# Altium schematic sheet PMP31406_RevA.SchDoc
size 431 x 279 mm; Date: Not shown in title block; ApprovedBy: Not shown in title block; CheckedBy: Not shown in title block; Author: Not shown in title block; CompanyName: Not shown in title block; Engineer: Not shown in title block; Organization: Not shown in title block; Address1: Not shown in title block; Address2: Not shown in title block; Address3: Not shown in title block; Address4: Not shown in title block; DocumentNumber: 2; Revision: Use project parameter SCH_Rev; SheetNumber: 1; SheetTotal: 1; PageSetup: Record=PageOptions¦CenterHorizontal=True¦CenterVertical=True¦PrintScale=1.00¦XCorrection=1.00¦YCorrection=1.00¦PrintKind=0¦BorderSize=5000000¦LeftOffset=0¦BottomOffset=0¦Orientation=2¦PaperLength=1000¦PaperWidth=1000¦Scale=100¦PaperSource=15¦PrintQuality=600¦MediaType=1¦DitherType=10¦PaperKind=Letter¦PrintScaleMode=1
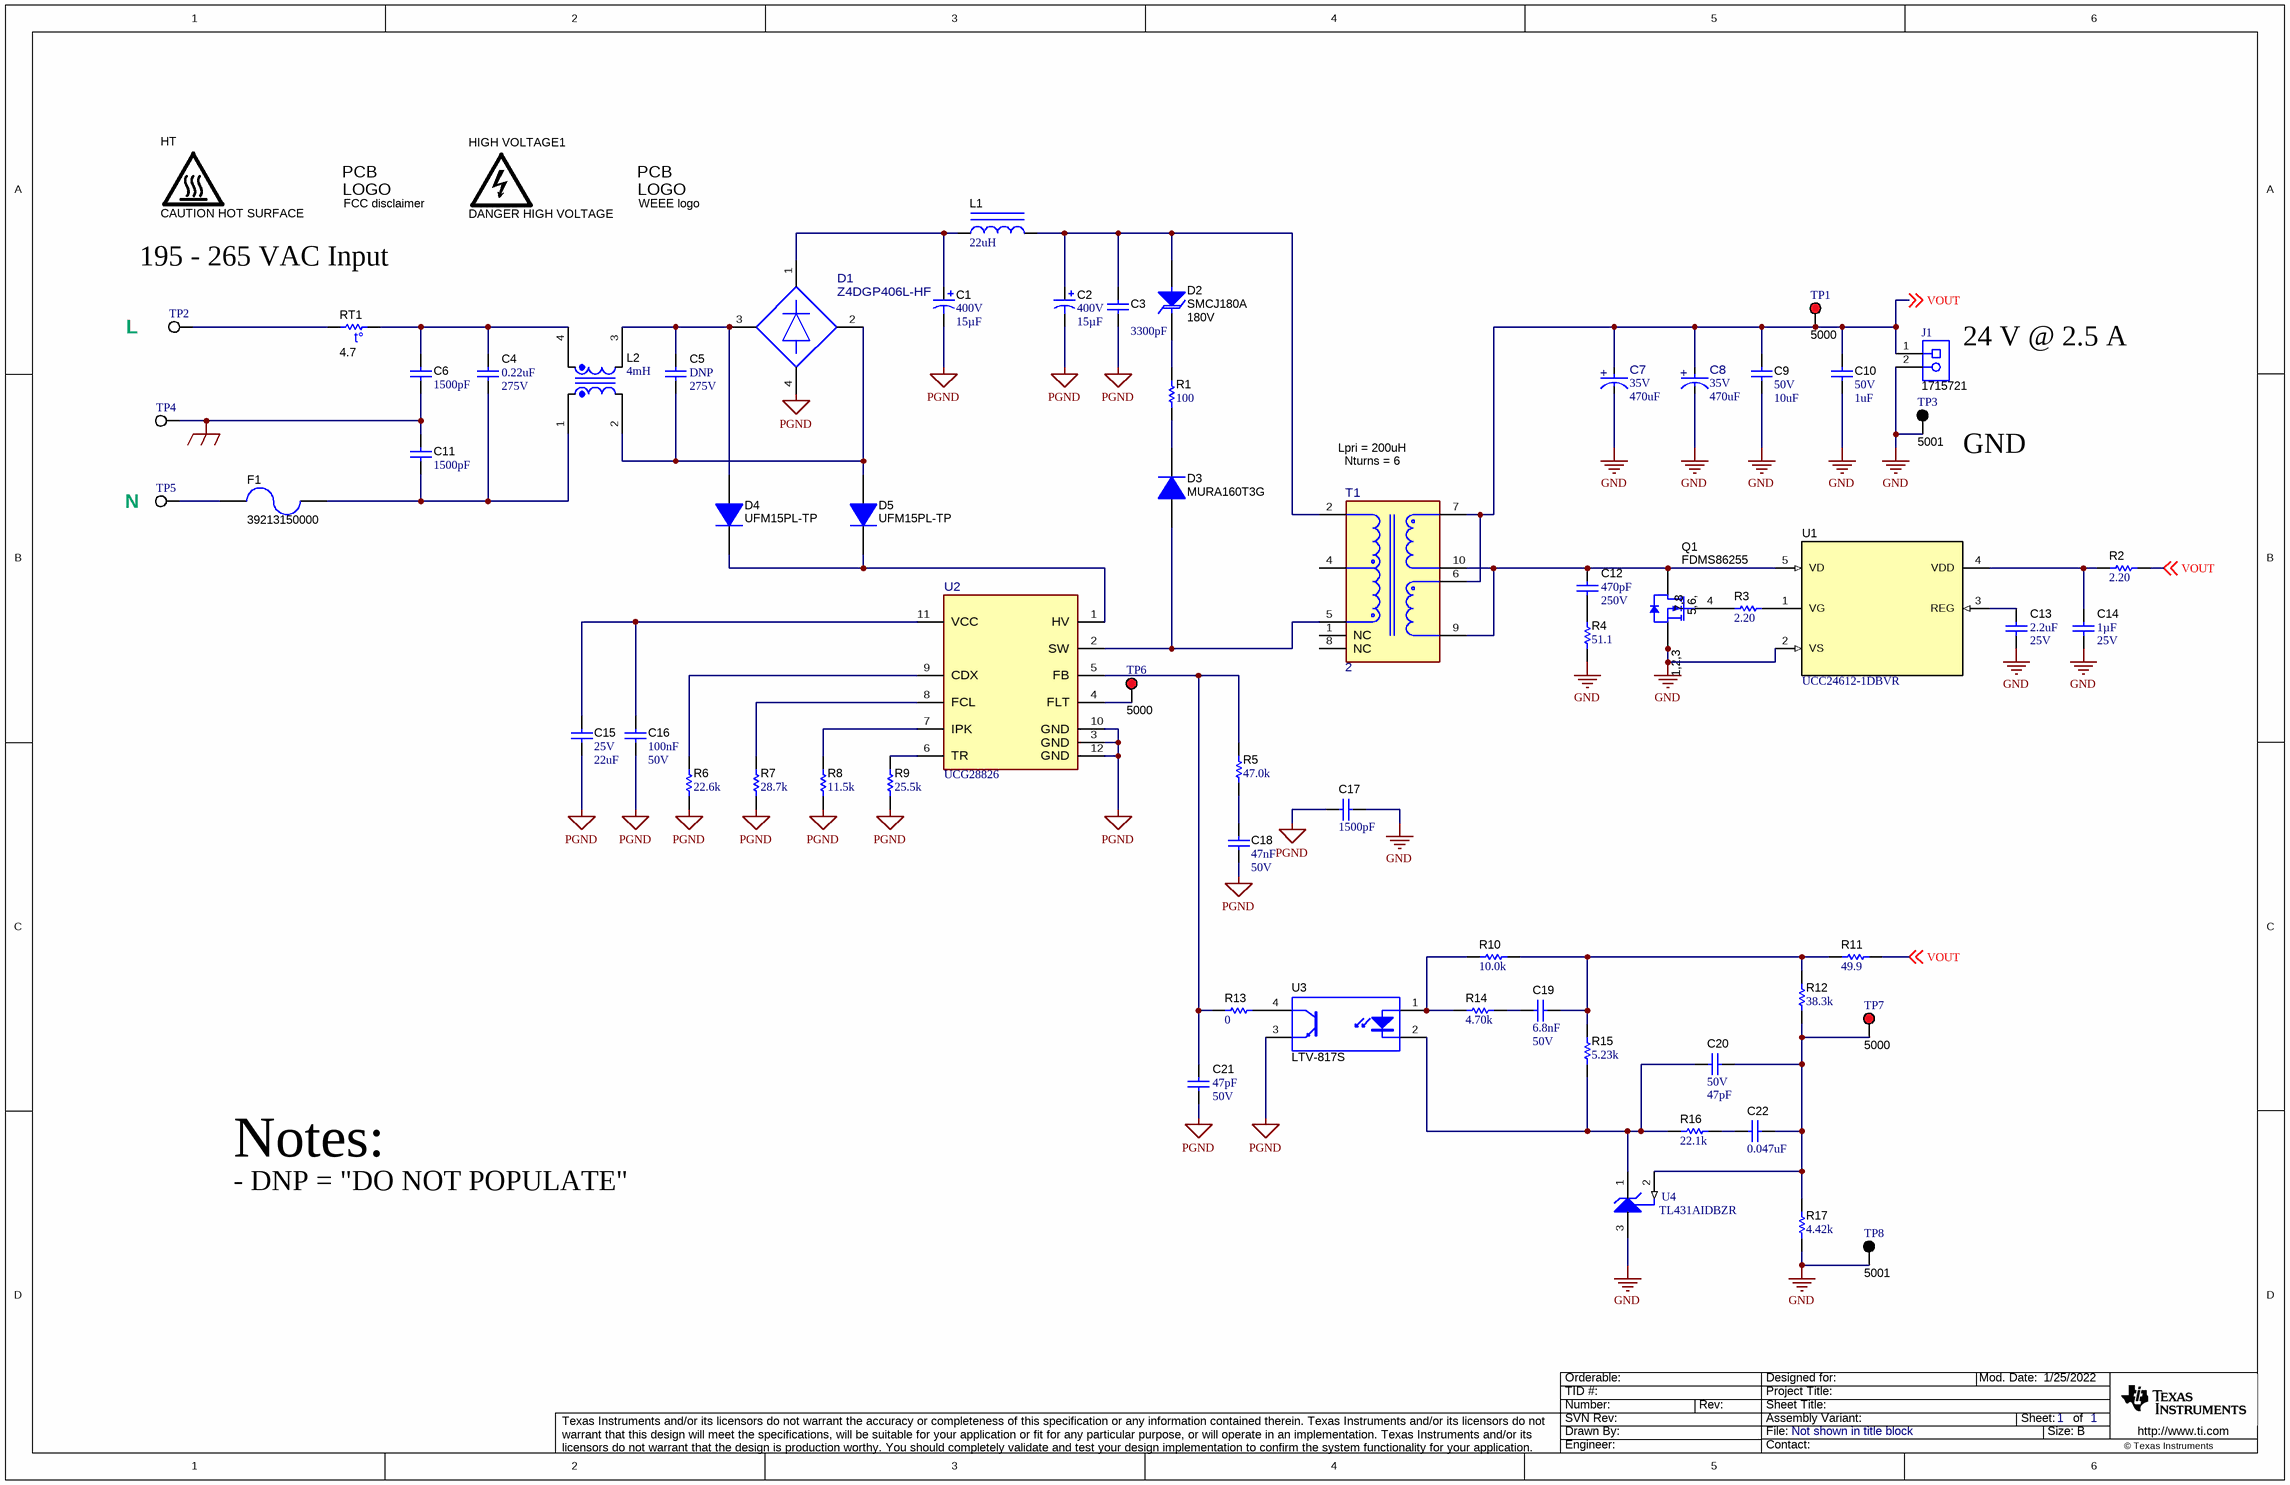
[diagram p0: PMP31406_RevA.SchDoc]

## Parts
?  FCC disclaimer  [FCC_disclaimer]  (no BOM)
C1  VDC_V: 400V  ValueDisplayed: 15µF  [UCS_1250x2000]  (hidden comment: UCS2G150MHD)
C2  VDC_V: 400V  ValueDisplayed: 15µF  [UCS_1250x2000]  (hidden comment: UCS2G150MHD)
C3  ValueDisplayed: 3300pF  [1206]  (hidden comment: GRM31BR73A332KW01L)
C4  VDC_V: 275V  ValueDisplayed: 0.22uF  [WCAP-FTX2_1500x700x1250]  (hidden comment: 890324024002)
C5  VDC_V: 275V  ValueDisplayed: DNP  [WCAP-FTX2_1500x700x1250]  (hidden comment: 890324024002)
C6  ValueDisplayed: 1500pF  [KY_700x500x1000]  (hidden comment: DE2E3KY152MN3AM02F)
C7  VDC_V: 35V  ValueDisplayed: 470uF  [FP-EEH-ZS1V471P_RADIAL-MFG]  (hidden comment: HHXJ350ARA471MJC5G)
C8  VDC_V: 35V  ValueDisplayed: 470uF  [FP-EEH-ZS1V471P_RADIAL-MFG]  (hidden comment: HHXJ350ARA471MJC5G)
C9  VDC_V: 50V  ValueDisplayed: 10uF  [1206_190]  (hidden comment: GCM31CD71H106K)
C10  VDC_V: 50V  ValueDisplayed: 1uF  [0805_HV]  (hidden comment: C2012X6S1H105K125AB)
C11  ValueDisplayed: 1500pF  [KY_700x500x1000]  (hidden comment: DE2E3KY152MN3AM02F)
C12  Cap_F: 470pF  VDC_V: 250V  [0603]  (hidden comment: GRM188R72E471KW07D)
C13  VDC_V: 25V  ValueDisplayed: 2.2uF  [0805_HV]  (hidden comment: GRM219R61E225KA12D)
C14  VDC_V: 25V  Cap_F: 1µF  [0603]  (hidden comment: C1608X7R1E105K080AE)
C15  VDC_V: 25V  ValueDisplayed: 22uF  [1210_270]  (hidden comment: TMK325B7226MM-TR)
C16  Cap_F: 100nF  VDC_V: 50V  [0603]  (hidden comment: 06035C104KAZ2A)
C17  ValueDisplayed: 1500pF  [KY_700x500x1000]  (hidden comment: DE2E3KY152MN3AM02F)
C18  Cap_F: 47nF  VDC_V: 50V  [0805_HV]  (hidden comment: 08055C473KAT2A)
C19  Cap_F: 6.8nF  VDC_V: 50V  [0603]  (hidden comment: C0603C682K5RACTU)
C20  VDC_V: 50V  ValueDisplayed: 47pF  [0603]  (hidden comment: CGA3E2NP01H470J080AA)
C21  VDC_V: 50V  ValueDisplayed: 47pF  [0603]  (hidden comment: CGA3E2NP01H470J080AA)
C22  ValueDisplayed: 0.047uF  [0603]  (hidden comment: C1608X5R1H473K080AA)
D1  Z4DGP406L-HF  [FP-Z4DGP406L-HF_SMT_8MM1_10MM5-MFG]
D2  SMCJ180A  value 180V  [SMC]
D3  MURA160T3G  [SMA]
D4  UFM15PL-TP  [SOD-123FL]
D5  UFM15PL-TP  [SOD-123FL]
F1  39213150000  [FUSE_392]
HIGH_VOLTAGE1  DANGER HIGH VOLTAGE  [IEC_HighVoltage_Medium]  (no BOM)
HT  CAUTION HOT SURFACE  [IEC_HotSurface_Medium]  (no BOM)
J1  1715721  [PhoenixContact_1715721]
L1  ValueDisplayed: 22uH  [WE-TI_5075]  (hidden comment: 7447462220)
L2  value 4mH  [WE-CMB_XS]  (hidden comment: 744821240)
Q1  FDMS86255  [TRANS_NexFET_Q5B]
R1  ValueDisplayed: 100  [1210]
R2  ValueDisplayed: 2.20  [0603]  (hidden comment: ERJ-3RQF2R2V)
R3  ValueDisplayed: 2.20  [0603]  (hidden comment: ERJ-3RQF2R2V)
R4  ValueDisplayed: 51.1  [1206]  (hidden comment: ERJ-8ENF51R1V)
R5  ValueDisplayed: 47.0k  [0603]  (hidden comment: CRCW060347K0FKEA)
R6  ValueDisplayed: 22.6k  [0603]  (hidden comment: CRCW060322K6FKEA)
R7  ValueDisplayed: 28.7k  [0603]  (hidden comment: CRCW060328K7FKEA)
R8  ValueDisplayed: 11.5k  [0603]  (hidden comment: CRCW060311K5FKEA)
R9  ValueDisplayed: 25.5k  [0603]  (hidden comment: CRCW060325K5FKEA)
R10  ValueDisplayed: 10.0k  [0603]  (hidden comment: M55342K12B10E0T)
R11  ValueDisplayed: 49.9  [0603]  (hidden comment: M55342K12B49D9T)
R12  ValueDisplayed: 38.3k  [0603]  (hidden comment: RC0603FR-0738K3L)
R13  ValueDisplayed: 0  [0603]  (hidden comment: RC0603JR-070RL)
R14  ValueDisplayed: 4.70k  [0603]  (hidden comment: RC0603FR-074K7L)
R15  ValueDisplayed: 5.23k  [0603]  (hidden comment: RC0603FR-075K23L)
R16  ValueDisplayed: 22.1k  [0603]  (hidden comment: RC0603FR-0722K1L)
R17  ValueDisplayed: 4.42k  [0603]  (hidden comment: RC0603FR-074K42L)
RT1  value 4.7  [S153]  (hidden comment: B57153S0479M000)
T1  2  [FP-8507142_PTH_XRMS_28MM8_28MM5-MFG]
TP1  5000  [Keystone5000]
TP2  5002  [Keystone5002]  (value not drawn)
TP3  5001  [Keystone5001]
TP4  5002  [Keystone5002]  (value not drawn)
TP5  5002  [Keystone5002]  (value not drawn)
TP6  5000  [Keystone5000]
TP7  5000  [Keystone5000]
TP8  5001  [Keystone5001]
U1  UCC24612-1DBVR  [DBV0005A_N]
U2  UCG28826  [REZ0012A-MFG]
U3  LTV-817S  [DIP254P762X350-4]
U4  TL431AIDBZR  [DBZ0003A_N]
x  WEEE logo  [WEEE_Minimum]  (no BOM)

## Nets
GND: C7.1(CATHODE) C8.1(CATHODE) C9.2 C10.2 C13.2 C14.2 C17.1 J1.2 Q1.1(S) Q1.2(S) Q1.3(S) R4.1 R17.1 TP3.1 TP8.1 U1.2(VS) U4.3(ANODE)
NetC6_2: C6.2 C11.1 TP4.1
PGND: C1.2(-) C2.2(-) C3.2 C15.2 C16.2 C17.2 C18.2 C21.2 D1.4(-) R6.1 R7.1 R8.1 R9.1 U2.3(GND) U2.10(GND) U2.12(GND) U3.3(E)
VOUT: C7.2(ANODE) C8.2(ANODE) C9.1 C10.1 J1.1 R2.2 R11.1 T1.6 T1.7 TP1.1 ; off-sheet VOUT
NetC1_1: C1.1(+) D1.1(+) L1.1
NetC2_1: C2.1(+) C3.1 D2.2(A) L1.2 T1.2
NetC4_1: C4.1 C6.1 L2.4 RT1.2
NetC4_2: C4.2 C11.2 F1.1 L2.1
NetC5_1: C5.1 D1.3(2_~) D4.2(A) L2.3
NetC5_2: C5.2 D1.2(1_~) D5.2(A) L2.2
NetC12_1: C12.1 Q1.5(D) Q1.6(D) Q1.7(D) Q1.8(D) T1.9 T1.10 U1.5(VD)
NetC12_2: C12.2 R4.2
NetC13_1: C13.1 U1.3(REG)
NetC14_1: C14.1 R2.1 U1.4(VDD)
NetC15_1: C15.1 C16.1 U2.11(VCC)
NetC18_1: C18.1 R5.1
NetC19_1: C19.1 R14.2
NetC19_2: C19.2 R10.1 R11.2 R12.2 R15.2
NetC20_1: C20.1 R15.1 R16.1 U3.2(K) U4.1(CATHODE)
NetC20_2: C20.2 C22.1 R12.1 R17.2 TP7.1 U4.2(REF)
NetC21_1: C21.1 R5.2 R13.1 U2.5(FB)
NetC22_2: C22.2 R16.2
NetD2_1: D2.1(K) R1.2
NetD3_1: D3.1(K) R1.1
NetD3_2: D3.2(A) T1.5 U2.2(SW)
NetD4_1: D4.1(K) D5.1(K) U2.1(HV)
NetF1_2: F1.2 TP5.1
NetQ1_4: Q1.4(G) R3.1
NetR3_2: R3.2 U1.1(VG)
NetR6_2: R6.2 U2.9(CDX)
NetR7_2: R7.2 U2.8(FCL)
NetR8_2: R8.2 U2.7(IPK)
NetR9_2: R9.2 U2.6(TR)
NetR10_2: R10.2 R14.1 U3.1(A)
NetR13_2: R13.2 U3.4(C)
NetRT1_1: RT1.1 TP2.1
NetTP6_1: TP6.1 U2.4(FLT)

Not connected (* = marked no-connect by the designer): T1 1(NC) 4 8(NC)

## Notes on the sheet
- 195 - 265 VAC Input
- (near TP2) L
- (near J1) 24 V @ 2.5 A
- (near TP5) N
- Lpri = 200uH
- (near T1) Nturns = 6
- (near TP3) GND
- Notes:
- - DNP = "DO NOT POPULATE"

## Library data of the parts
? = CMP-0074847-1: FCC_disclaimer; Library Reference: Logo
C1 C2 = CMP-0081925-1: CAP, AL, 15 µF, 400 V, +/- 20%, TH; Manufacturer: Nichicon; TaMin_C: -40°C; Polarized: Y; SizeAreaWB_mm2: 210.25; U/M: EA; Value: 15uF; TaMax_C: 105°C; SizeZ_mm: 21.5; SizeX_mm: 12.5; Cap_Case: 12.5x20mm; SizeArea_mm2: 156.25; CompType: Capacitor; AEC Qualified: N; Cap_F: 22µF
C3 = CMP-0008919-2: CAP, CERM, 3300 pF, 1000 V, +/- 10%, X7R, 1206; Manufacturer: MuRata; TaMin_C: -55°C; Polarized: N; SizeAreaWB_mm2: 10.92; Value1: Unknown; U/M: EA; Value: 3300pF; TaMax_C: 125°C; SizeZ_mm: 1.35; SizeX_mm: 3.2; SizeY_mm: 1.6; Value2: 1000V; SizeArea_mm2: 5.12; Cap_F: 3.3nF; VDC_V: 1kV; AEC Category: Q200
C4 C5 = CMP-0012312-3: CAP, Film, 0.22 uF, 275 V, +/- 10%, TH; Manufacturer: Wurth Elektronik; TaMin_C: -40°C; Polarized: N; SizeAreaWB_mm2: 153; Value1: Unknown; Value: 0.22uF; TaMax_C: 105°C; SizeZ_mm: 13; SizeX_mm: 15; SizeY_mm: 7; Cap_Case: 15x7x12.5; SizeArea_mm2: 105; Cap_F: 220nF; AEC Category: Q200
C6 C11 C17 = CMP-0009609-4: CAP, CERM, 1500 pF, X1 250 VAC/Y2 300 VAC, +/- 20%, E, TH; Manufacturer: MuRata; TaMin_C: -25°C; Polarized: N; SizeAreaWB_mm2: 66.5; Value1: Unknown; U/M: EA; Value: 1500pF; TaMax_C: 85°C; SizeZ_mm: 10; SizeX_mm: 7.5; SizeY_mm: 5; Cap_Case: 7x5x10mm; SizeArea_mm2: 37.5; Cap_F: 1.5nF; AEC Category: Q200; AC_Safety: X1Y2; VAC_X: 250V; VAC_Y: 300V
C7 C8 = CMP-0090467-1: Tolerance_%: 20%; Life: 4000Hours; AEC Grade: Grade 1; Cap_F: 470µF; IRMS_A: 4A; Dissipation Factor: 12%; Leakage Current: 164.5uA; Value: 470uF; SizeZ_mm: 16.8mm; Esr: 11m; AEC Qualified: Yes
C9 = CMP-0008808-1: CAP, CERM, 10 uF, 50 V, +/- 10%, X7T, 1206_190; Manufacturer: MuRata; TaMin_C: -55°C; Polarized: N; SizeAreaWB_mm2: 10.92; Value1: Unknown; U/M: EA; Value: 10uF; TaMax_C: 125°C; SizeZ_mm: 1.9; SizeX_mm: 3.2; SizeY_mm: 1.6; Cap_Case: 1206; SizeArea_mm2: 5.12; Cap_F: 10µF; AEC Category: Q200
C10 = CMP-0007855-1: CAP, CERM, 1 uF, 50 V, +/- 10%, X6S, 0805; Manufacturer: TDK; TaMin_C: -55°C; ESR_ohm: 8.782m; Polarized: N; SizeAreaWB_mm2: 6.75; Value1: 0.008782 ohm; U/M: EA; Value: 1uF; TaMax_C: 105°C; SizeZ_mm: 1.45; SizeX_mm: 2; SizeY_mm: 1.25; Cap_Case: 0805; SizeArea_mm2: 2.5; Cap_F: 1µF; IRMS_A: 2.2049A; AEC Category: Q200
C12 = CMP-0007495-4: CAP, CERM, 470 pF, 250 V, +/- 10%, X7R, 0603; Manufacturer: MuRata; TaMin_C: -55°C; Polarized: N; SizeAreaWB_mm2: 4.68; Value1: Unknown; U/M: EA; Value: 470pF; TaMax_C: 125°C; SizeZ_mm: 1; SizeX_mm: 1.6; SizeY_mm: 0.8; SizeArea_mm2: 1.28; AEC Category: Q200
C13 = CMP-0008208-2: CAP, CERM, 2.2 uF, 25 V, +/- 10%, X5R, 0805; Manufacturer: MuRata; TaMin_C: -55°C; ESR_ohm: 6m; Polarized: N; SizeAreaWB_mm2: 6.75; Value1: 0.006 ohm; U/M: EA; Value: 2.2uF; TaMax_C: 85°C; SizeZ_mm: 1.45; SizeX_mm: 2; SizeY_mm: 1.25; Cap_Case: 0805; SizeArea_mm2: 2.5; Cap_F: 2.2µF; AEC Category: Q200
C14 = CMP-0860549-1: CAP, CERM, 1 µF, 25 V,+/- 10%, X7R, 0603; Manufacturer: TDK; SizeZ_mm: 1; AEC Qualified: N; SizeX_mm: 1.6; TaMin_C: -55°C; U/M: EA; SizeY_mm: 0.8; SizeAreaWB_mm2: 4.68; AEC Category: Q200; SizeArea_mm2: 1.28; Value: 1uF; TaMax_C: 125°C
C15 = CMP-0009256-2: CAP, CERM, 22 uF, 25 V, +/- 20%, X7R, 1210; Manufacturer: Taiyo Yuden; TaMin_C: -55°C; Polarized: N; SizeAreaWB_mm2: 14.7; Value1: Unknown; U/M: EA; Value: 22uF; TaMax_C: 125°C; SizeZ_mm: 2.7; SizeX_mm: 3.2; SizeY_mm: 2.5; Cap_Case: 1210; SizeArea_mm2: 8; Cap_F: 22µF; AEC Category: Q200
C16 = CMP-0079095-1: CAP, CERM, 0.1 µF, 50 V,+/- 10%, X7R, AEC-Q200 Grade 1, 0603; Manufacturer: AVX; SizeAreaWB_mm2: 4.68; SizeArea_mm2: 1.28; AEC Qualified: Y; AEC Category: Q200; Value: 0.1uF; TaMax_C: 125°C; SizeZ_mm: 1; Polarized: N; TaMin_C: -55°C; SizeY_mm: 0.8; U/M: EA; SizeX_mm: 1.6; ValueDisplayed: 0.1µF
C18 = CMP-0007659-2: CAP, CERM, 0.047 uF, 50 V, +/- 10%, X7R, 0805; Manufacturer: AVX; TaMin_C: -55°C; ESR_ohm: 35m; Polarized: N; SizeAreaWB_mm2: 6.75; Value1: 0.035 ohm; U/M: EA; TaMax_C: 125°C; SizeZ_mm: 1.45; SizeX_mm: 2; SizeY_mm: 1.25; Cap_Case: 0805; SizeArea_mm2: 2.5; AEC Category: Q200
C19 = CMP-0006963-4: CAP, CERM, 6800 pF, 50 V, +/- 10%, X7R, 0603; Manufacturer: Kemet; TaMin_C: -55°C; Polarized: N; SizeAreaWB_mm2: 4.68; Value1: Unknown; U/M: EA; Value: 6800pF; TaMax_C: 125°C; SizeZ_mm: 1; SizeX_mm: 1.6; SizeY_mm: 0.8; SizeArea_mm2: 1.28; AEC Category: Q200
C20 C21 = CMP-0080062-1: CAP, CERM, 47 pF, 50 V,+/- 5%, C0G/NP0, AEC-Q200 Grade 0, 0603; Manufacturer: TDK; TaMin_C: -55°C; Polarized: N; SizeAreaWB_mm2: 4.68; U/M: EA; Value: 47pF; TaMax_C: 150°C; SizeZ_mm: 1; SizeX_mm: 1.6; SizeY_mm: 0.8; SizeArea_mm2: 1.28; AEC Qualified: Y; AEC Grade: 0; AEC Category: Q200
C22 = CMP-0007015-5: CAP, CERM, 0.047 uF, 50 V, +/- 10%, X5R, 0603; Manufacturer: TDK; TaMin_C: -55°C; ESR_ohm: 49.007m; Polarized: N; SizeAreaWB_mm2: 4.68; Value1: 0.049007 ohm; U/M: EA; TaMax_C: 85°C; SizeZ_mm: 1; SizeX_mm: 1.6; SizeY_mm: 0.8; Value2: 50V; SizeArea_mm2: 1.28; Cap_F: 47nF; IRMS_A: 767.528mA; AEC Category: Q200
D1 = CMP-0120719-1: Bridge Rectifier Single Phase Standard 600 V Surface Mount Z4-D; Manufacturer: Comchip; AEC Qualified: No; SizeZ_mm: 1.45mm; TJmax_C: 175°C; Vf_V: 600V; Cap_F: 45pF; Forward Current: 4A; Max Surge Forward Current: 150A; Peak Reverse Current: 0.08uA
D2 = CMP-0065113-3: Diode, TVS, Uni, 180 V, SMC; Manufacturer: Littelfuse; AEC Qualified: N; RJA_CperW: 75; Value1: 1500W; Ppk: 1.5kW; SizeAreaWB_mm2: 83.2686; SizeX_mm: 8.13; Ipp: 4.6A; AEC Category: Q101; SizeY_mm: 6.22; SizeZ_mm: 2.6; SizeArea_mm2: 50.5686
D3 = CMP-0029033-2: Diode, Ultrafast, 600 V, 1 A, AEC-Q101, SMA; Manufacturer: ON Semiconductor; AEC Category: Q101; SizeX_mm: 5.59; Io_A: 1A; Green_Lifecycle: Active; Value2: 1.05V; SizeArea_mm2: 16.3228; SizeZ_mm: 2.87; TJmax_C: 175°C; Value: 600V; AEC Qualified: Y; SizeAreaWB_mm2: 37.3428; SizeY_mm: 2.92; Green_REACh: Passed
D4 D5 = CMP-0029148-2: Diode, Ultrafast, 600 V, 1 A, SOD-123FL; Manufacturer: Micro Commercial Components; SizeY_mm: 1.65; Value: 600V; Io_A: 1A; Green_Lifecycle: Not Set; Green_REACh: Incomplete; SizeX_mm: 3.6; SizeAreaWB_mm2: 12.19; SizeArea_mm2: 5.94; AEC Qualified: N; Value2: 1.7V; SizeZ_mm: 0.98; AEC Category: Q101; TJmax_C: 150°C
F1 = CMP-0003561-2: Fuse, 3.15 A, 250VAC/VDC, TH; Manufacturer: Littelfuse; Irating_A: 3.15A; VAC_V: 250V
HIGH_VOLTAGE1 = CMP-0074835-1: IEC 61010-1 High Voltage Warning; SymbolCreator: a0412235
HT = CMP-0074837-1: IEC 61010-1 Hot Surface Warning; SymbolCreator: a0412235
J1 = CMP-0055471-1: Terminal Block, 5.08 mm, 2x1, TH; Manufacturer: Phoenix Contact; Cert_VDE: Y; CNHeader: FALSE; Current_A: 17.5A; Green_Lifecycle: Not Set; Gender: Female; Cert_CULUS: N; Green_REACh: Incomplete; Voltage_V: 400V; Row_Count: 1; Pitch_mm: 5.08; ContactFinish: Tin; CT: TRUE
L1 = CMP-0064517-1: Inductor, Unshielded Drum Core, Ferrite, 22 uH, 1.7 A, 0.102 ohm, TH; Manufacturer: Wurth Elektronik; Isat: 1.7A @ 10% inductance drop; Irms: 1.8A @ 40C rise; Green_Lifecycle: Active; SizeAreaWB_mm2: 64; DCR_ohm: 0.102; Green_REACh: Passed; Value: 22uH; Imax_A: 1.7A; SizeZ_mm: 8.5; SizeX_mm: 6; SizeArea_mm2: 36; Ind_H: 22µH; AEC Category: Q200
L2 = CMP-0076848-1: Coupled inductor, 4 mH, 1.5 A, 0.14 ohm, TH; Manufacturer: Wurth Elektronik; SizeAreaWB_mm2: 161.5; SizeArea_mm2: 112.5; AEC Qualified: N; AEC Category: Q200; SizeZ_mm: 20.5; SizeY_mm: 7.5; DCR_ohm: 0.14; SizeX_mm: 15.0
Q1 = CMP-0001059-1: MOSFET, N-CH, 150 V, 10 A, SON 5x6mm; Alternate Manufacturer: None; Manufacturer: Fairchild Semiconductor; SizeZ_mm: 1.05; ChType: N; Value2: 45 nC; VdsMax_V: 150V; SizeX_mm: 6.1; SizeY_mm: 5.1; Vgs_V: 20V; QgTyp_nC: 45; Value: 150V; SizeArea_mm2: 31.11; AEC Category: Q101; IdsMax_A: 10A; SizeAreaWB_mm2: 57.51; U/M: EA
R1 = CMP-0083444-1: RES, 100, 5%, 0.5 W, 1210; Manufacturer: Yageo; Power_W: 500mW; TempCo: 200 ppm/C; SizeAreaWB_mm2: 14.7; Value_Code: 100R0; Value: 100; EIA_Code: E24; Res_ohm: 10; SizeX_mm: 3.2; SizeY_mm: 2.5; SizeZ_mm: 1.35; Value2: 0.5W; SizeArea_mm2: 8; AEC Qualified: N
R2 R3 = CMP-0022711-2: RES, 2.20, 1%, 0.1 W, 0603; Manufacturer: Panasonic; Power_W: 100mW; TempCo: 200 ppm/C; Value_Code: 2R20; U/M: EA; Value: 2.20; Res_ohm: 2.2; SizeX_mm: 1.6; SizeY_mm: 0.8; SizeZ_mm: 1; Value2: 0.1W; SizeArea_mm2: 1.28; AEC Category: Q200
R4 = CMP-0017637-3: RES, 51.1, 1%, 0.25 W, AEC-Q200 Grade 0, 1206; Manufacturer: Panasonic; Power_W: 250mW; TempCo: 100 ppm/C; Value_Code: 51R1; Value: 51.1; EIA_Code: E96; SizeX_mm: 3.2; SizeY_mm: 1.6; SizeZ_mm: 1.35; Value2: 0.25W; SizeArea_mm2: 5.12; AEC Qualified: Y; VDC_V: 200V; AEC Category: Q200; AEC Grade: 0; SizeAreaWB_mm2: 10.92
R5 = CMP-0022438-1: RES, 47.0 k, 1%, 0.1 W, AEC-Q200 Grade 0, 0603; Manufacturer: Vishay-Dale; Power_W: 100mW; TempCo: 100 ppm/C; Value_Code: 47k0; U/M: EA; Value: 47.0k; Res_ohm: 47k; SizeX_mm: 1.6; SizeY_mm: 0.8; SizeZ_mm: 1; Value2: 0.1W; SizeArea_mm2: 1.28; AEC Qualified: Y; VDC_V: 75V; AEC Grade: 0; AEC Category: Q200
R6 = CMP-0022221-4: RES, 22.6 k, 1%, 0.1 W, AEC-Q200 Grade 0, 0603; Manufacturer: Vishay-Dale; Power_W: 100mW; TempCo: 100 ppm/C; Value_Code: 22k6; Value: 22.6k; EIA_Code: E96; SizeX_mm: 1.6; SizeY_mm: 0.8; SizeZ_mm: 1; Value2: 0.1W; SizeArea_mm2: 1.28; AEC Qualified: Y; VDC_V: 75V; AEC Category: Q200; AEC Grade: 0
R7 = CMP-0022261-1: RES, 28.7 k, 1%, 0.1 W, 0603; Manufacturer: Vishay-Dale; Power_W: 100mW; TempCo: 100 ppm/C; Value_Code: 28k7; U/M: EA; Value: 28.7k; EIA_Code: E96; SizeX_mm: 1.6; SizeY_mm: 0.8; SizeZ_mm: 1; Value2: 0.1W; SizeArea_mm2: 1.28; VDC_V: 75V; AEC Category: Q200
R8 = CMP-0022018-1: RES, 11.5 k, 1%, 0.1 W, 0603; Manufacturer: Vishay-Dale; Power_W: 100mW; TempCo: 100 ppm/C; Value_Code: 11k5; U/M: EA; Value: 11.5k; EIA_Code: E96; SizeX_mm: 1.6; SizeY_mm: 0.8; SizeZ_mm: 1; Value2: 0.1W; SizeArea_mm2: 1.28; VDC_V: 75V; AEC Category: Q200
R9 = CMP-0022242-1: RES, 25.5 k, 1%, 0.1 W, 0603; Manufacturer: Vishay-Dale; Power_W: 100mW; TempCo: 100 ppm/C; Value_Code: 25k5; U/M: EA; Value: 25.5k; EIA_Code: E96; SizeX_mm: 1.6; SizeY_mm: 0.8; SizeZ_mm: 1; Value2: 0.1W; SizeArea_mm2: 1.28; VDC_V: 75V; AEC Category: Q200
R10 = CMP-0080488-1: RES, 10.0 k, 1%, 0.1 W, 0603; Manufacturer: TT Electronics/IRC; Power_W: 100mW; TempCo: 100 ppm/C; SizeAreaWB_mm2: 4.68; Value_Code: 10k0; Value: 10.0k; EIA_Code: E96; Res_ohm: 10k; SizeX_mm: 1.6; SizeY_mm: 0.8; SizeZ_mm: 1; Value2: 0.1W; SizeArea_mm2: 1.28; AEC Qualified: N; AEC Category: Q200
R11 = CMP-0080492-1: RES, 49.9, 1%, 0.1 W, 0603; Manufacturer: TT Electronics/IRC; Power_W: 100mW; TempCo: 100 ppm/C; SizeAreaWB_mm2: 4.68; Value_Code: 49R9; Value: 49.9; EIA_Code: E96; SizeX_mm: 1.6; SizeY_mm: 0.8; SizeZ_mm: 1; Value2: 0.1W; SizeArea_mm2: 1.28; AEC Qualified: N; AEC Category: Q200
R12 = CMP-0023066-5: RES, 38.3 k, 1%, 0.1 W, 0603; Manufacturer: Yageo; Power_W: 100mW; TempCo: 100 ppm/C; Value_Code: 38k3; Value: 38.3k; EIA_Code: E96; SizeX_mm: 1.6; SizeY_mm: 0.8; SizeZ_mm: 1; Value2: 0.1W; SizeArea_mm2: 1.28; AEC Qualified: N; VDC_V: 75V; AEC Category: Q200; SizeAreaWB_mm2: 4.68
R13 = CMP-0025885-5: RES, 0, 5%, 0.1 W, 0603; Manufacturer: Yageo; Power_W: 100mW; TempCo: 200 ppm/C; Value_Code: 0000; Value: 0; EIA_Code: E24; SizeX_mm: 1.6; SizeZ_mm: 1; Value2: 0.1W; SizeArea_mm2: 1.28; AEC Qualified: N; VDC_V: 75V; AEC Category: Q200; SizeY_mm: 0.8; SizeAreaWB_mm2: 4.68
R14 = CMP-0023153-5: RES, 4.70 k, 1%, 0.1 W, 0603; Manufacturer: Yageo; Power_W: 100mW; TempCo: 100 ppm/C; Value_Code: 4k70; Value: 4.70k; Res_ohm: 4.7k; SizeX_mm: 1.6; SizeY_mm: 0.8; SizeZ_mm: 1; Value2: 0.1W; SizeArea_mm2: 1.28; AEC Qualified: N; VDC_V: 75V; AEC Category: Q200; SizeAreaWB_mm2: 4.68
R15 = CMP-0023199-5: RES, 5.23 k, 1%, 0.1 W, 0603; Manufacturer: Yageo; Power_W: 100mW; TempCo: 100 ppm/C; Value_Code: 5k23; Value: 5.23k; EIA_Code: E96; SizeX_mm: 1.6; SizeY_mm: 0.8; SizeZ_mm: 1; Value2: 0.1W; SizeArea_mm2: 1.28; AEC Qualified: N; VDC_V: 75V; AEC Category: Q200; SizeAreaWB_mm2: 4.68
R16 = CMP-0022923-5: RES, 22.1 k, 1%, 0.1 W, 0603; Manufacturer: Yageo; Power_W: 100mW; TempCo: 100 ppm/C; Value_Code: 22k1; Value: 22.1k; EIA_Code: E96; SizeX_mm: 1.6; SizeY_mm: 0.8; SizeZ_mm: 1; Value2: 0.1W; SizeArea_mm2: 1.28; AEC Qualified: N; VDC_V: 75V; AEC Category: Q200; SizeAreaWB_mm2: 4.68
R17 = CMP-0023149-5: RES, 4.42 k, 1%, 0.1 W, 0603; Manufacturer: Yageo; Power_W: 100mW; TempCo: 100 ppm/C; Value_Code: 4k42; Value: 4.42k; EIA_Code: E96; SizeX_mm: 1.6; SizeY_mm: 0.8; SizeZ_mm: 1; Value2: 0.1W; SizeArea_mm2: 1.28; AEC Qualified: N; VDC_V: 75V; AEC Category: Q200; SizeAreaWB_mm2: 4.68
RT1 = CMP-0002555-2: Thermistor NTC, 4.70 ohm, 20%, 8.5mm Disc; Manufacturer: TDK; TaMax_C: 170°C; TaMin_C: -55°C; Power_W: 1.4W; U/M: EA
T1 = CMP-0124299-1: TRANSFORMER G254013LF; Manufacturer: GCI; SizeZ_mm: 20.8mm
TP1 TP7 = CMP-0055137-1: Test Point, Miniature, Red, TH; Manufacturer: Keystone; CNHeader: FALSE; Green_Lifecycle: Active; Green_REACh: Passed; ContactFinish: Silver; CT: TRUE
TP2 TP4 TP5 = CMP-0055139-2: Test Point, Miniature, White, TH; Manufacturer: Keystone Electronics; ContactFinish: Silver; Green_REACh: Passed; CT: TRUE; Green_Lifecycle: Active; CNHeader: FALSE
TP3 TP8 = CMP-0055138-2: Test Point, Miniature, Black, TH; Manufacturer: Keystone Electronics; ContactFinish: Silver; CNHeader: FALSE; Green_Lifecycle: Active; Green_REACh: Passed; CT: TRUE
TP6 = CMP-0055137-2: Test Point, Miniature, Red, TH; Manufacturer: Keystone Electronics; Green_REACh: Passed; Green_Lifecycle: Active; ContactFinish: Silver; CNHeader: FALSE; CT: TRUE
U1 = CMP-0013050-3: High-Frequency Multi-Mode Synchronous Rectifier Controller, DBV0005A (SOT-23-5); Manufacturer: Texas Instruments; Alternate PartNumber: UCC24612-1DBVT; SizeX_mm: 2.8; SizeY_mm: 2.9; CompType: IC; SizeZ_mm: 1.45; SizeArea_mm2: 8.12; SizeAreaWB_mm2: 14.82; AEC Category: Q200; AEC Qualified: N
U2 = CMP-0122264-1: Manufacturer: Texas Instruments; SizeZ_mm: 1mm; AEC Qualified: No; AEC Grade: NA; Standoff Height: 0mm
U3 = CMP-0006158-3: Optocoupler, 5 kV, 50-600% CTR, SMT; Manufacturer: Lite-On; CTR (Max): 600%; SizeAreaWB_mm2: 80.256; CTR (Min): 50%; SizeZ_mm: 4.6; SizeX_mm: 10.16; SizeArea_mm2: 46.736; Voltage_Isolation_Vrms: 5kV
U4 = CMP-0033090-1: Adjustable Precision Shunt Regulator, 34 ppm / degC, 100 mA, -40 to 85 degC, 3-pin SOT-23 (DBZ), Green (RoHS & no Sb/Br); Manufacturer: Texas Instruments; Iout/Iz(Max)(mA): 100; VO Adj(Max)(V): 36; Min Iz for Regulation(uA): 600; Temp Coeff(Typ)(ppm/ degree C): 34; Initial Accuracy @ 25/deg C(%): 1; SubFamily: Shunt Voltage Reference; Rating: Catalog; VO Adj(Min)(V): 2.495; Temp Coeff(Max)(ppm/ degree C): 92
x = CMP-0074769-1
